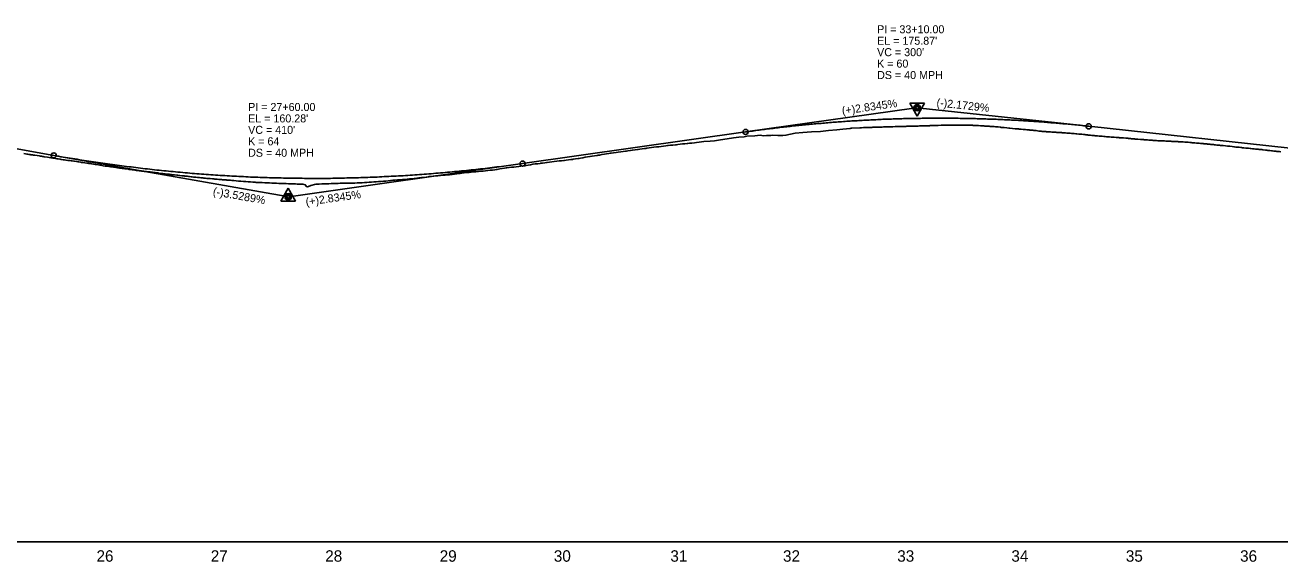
# Model space of a CAD drawing. Extents: x 1778432 to 1784301, y 601022 to 621789.
# Drawn here: x 1782073 to 1783170, y 620022 to 620491 of the extents above; entities that cross this region are included whole.
import ezdxf

# ---------------------------------------------------------------- set-up
doc = ezdxf.new("R2010")
doc.units = 0
for name, color, linetype in [('Exist Profile Cell', 7, 'Continuous'), ('Exist Vertical Profile Ground Line', 7, 'Continuous'), ('Exist Vertical Profile Horizontal Axis Label Major', 7, 'Continuous'), ('Prop PFL VPI Symbol CELL', 7, 'Continuous'), ('Prop Vertical Profile Curve Label', 7, 'Continuous'), ('Prop Vertical Profile Grade', 7, 'Continuous'), ('Prop Vertical Profile Grade Label', 7, 'Continuous'), ('Prop VPI Label', 7, 'Continuous')]:
    doc.layers.add(name, color=color, linetype=linetype)

msp = doc.modelspace()

# ---------------------------------------------------------------- linework, layer by layer
at = {"layer": 'Exist Profile Cell'}
msp.add_line((1780143, 620039.2), (1783681.5, 620039.2), dxfattribs=at)
at = {"layer": 'Exist Vertical Profile Ground Line'}
msp.add_lwpolyline([(1782071.8, 620378.3), (1782073.3, 620378.1), (1782074.5, 620378), (1782075.2, 620377.9), (1782076.2, 620377.7), (1782077.4, 620377.5), (1782078, 620377.4), (1782078.9, 620377.3), (1782079.4, 620377.2), (1782080.4, 620377.1), (1782081.4, 620376.9), (1782083.5, 620376.6), (1782085.5, 620376.3), (1782085.8, 620376.2), (1782086.4, 620376.1), (1782087, 620376.1), (1782087.5, 620376), (1782087.9, 620375.9), (1782088.9, 620375.8), (1782089.6, 620375.6), (1782092.5, 620375.2), (1782094.1, 620374.9), (1782095.4, 620374.7), (1782096, 620374.7), (1782097.1, 620374.5), (1782098.4, 620374.3), (1782100.8, 620373.9), (1782101.7, 620373.8), (1782103.6, 620373.4), (1782104.4, 620373.3), (1782106.3, 620373), (1782106.8, 620372.9), (1782107.3, 620372.9), (1782108.7, 620372.7), (1782110.3, 620372.4), (1782110.9, 620372.3), (1782112.1, 620372.2), (1782113.3, 620372), (1782114.1, 620371.9), (1782115.5, 620371.7), (1782116.3, 620371.6), (1782117.8, 620371.4), (1782119.2, 620371.2), (1782119.5, 620371.1), (1782120, 620371.1), (1782121.6, 620370.8), (1782122.2, 620370.7), (1782123.2, 620370.6), (1782125.2, 620370.3), (1782126.8, 620370.1), (1782128.2, 620369.9), (1782128.6, 620369.8), (1782129.2, 620369.7), (1782130.2, 620369.6), (1782131.2, 620369.4), (1782134.2, 620368.9), (1782134.8, 620368.8), (1782137.2, 620368.5), (1782138.4, 620368.3), (1782139.7, 620368.1), (1782140.1, 620368), (1782141.2, 620367.8), (1782143.1, 620367.5), (1782145.1, 620367.3), (1782146.1, 620367.1), (1782147.6, 620366.9), (1782148.3, 620366.8), (1782149.1, 620366.7), (1782150.3, 620366.5), (1782152.2, 620366.2), (1782153.9, 620366), (1782155, 620365.8), (1782155.7, 620365.7), (1782156.8, 620365.6), (1782157.3, 620365.5), (1782158, 620365.4), (1782160.3, 620365.1), (1782161.3, 620365), (1782163.4, 620364.7), (1782164, 620364.6), (1782166, 620364.4), (1782167, 620364.2), (1782168.8, 620364), (1782169.9, 620363.8), (1782170.5, 620363.7), (1782172.1, 620363.6), (1782172.5, 620363.5), (1782172.9, 620363.4), (1782174.5, 620363.2), (1782175.1, 620363.1), (1782175.9, 620363), (1782176.6, 620362.9), (1782177.4, 620362.8), (1782178.9, 620362.6), (1782179.6, 620362.5), (1782180.9, 620362.4), (1782181.9, 620362.3), (1782182.8, 620362.1), (1782184.1, 620362), (1782184.9, 620361.9), (1782186.4, 620361.7), (1782187, 620361.6), (1782188.2, 620361.5), (1782188.5, 620361.4), (1782189.1, 620361.4), (1782189.7, 620361.3), (1782191.1, 620361.1), (1782192.9, 620360.9), (1782193.2, 620360.9), (1782193.8, 620360.8), (1782194.1, 620360.8), (1782195.3, 620360.6), (1782197.4, 620360.4), (1782198.9, 620360.3), (1782199.5, 620360.2), (1782200.2, 620360.1), (1782200.8, 620360), (1782201.5, 620359.9), (1782202.1, 620359.9), (1782203, 620359.8), (1782203.6, 620359.7), (1782205.7, 620359.5), (1782206.1, 620359.4), (1782206.6, 620359.4), (1782207.8, 620359.3), (1782208.4, 620359.2), (1782209.9, 620359), (1782212, 620358.8), (1782212.7, 620358.7), (1782214, 620358.5), (1782215, 620358.5), (1782216.1, 620358.3), (1782216.8, 620358.3), (1782218.3, 620358), (1782219, 620358), (1782220.2, 620357.9), (1782220.9, 620357.8), (1782222.3, 620357.7), (1782223.8, 620357.5), (1782224.4, 620357.5), (1782225.4, 620357.4), (1782226.7, 620357.3), (1782227.5, 620357.2), (1782228.5, 620357.1), (1782229.2, 620357), (1782229.9, 620356.9), (1782230.6, 620356.9), (1782232, 620356.7), (1782232.7, 620356.7), (1782233.5, 620356.6), (1782234.8, 620356.5), (1782236.8, 620356.3), (1782237.3, 620356.3), (1782237.9, 620356.2), (1782238.9, 620356.1), (1782239.4, 620356.1), (1782239.9, 620356), (1782240.9, 620355.9), (1782242.4, 620355.8), (1782243.2, 620355.7), (1782244.1, 620355.7), (1782245.1, 620355.6), (1782245.4, 620355.5), (1782247.2, 620355.4), (1782247.9, 620355.3), (1782248.7, 620355.3), (1782249.3, 620355.2), (1782251.3, 620355.1), (1782252.6, 620355), (1782253.7, 620354.9), (1782254.5, 620354.8), (1782255.5, 620354.8), (1782257.4, 620354.6), (1782259.6, 620354.4), (1782261.7, 620354.2), (1782263.8, 620354.1), (1782265.9, 620353.9), (1782268.1, 620353.7), (1782270, 620353.6), (1782272.1, 620353.4), (1782274.2, 620353.3), (1782275, 620353.2), (1782276.2, 620353.2), (1782278.3, 620353.1), (1782279.6, 620353), (1782280.4, 620353), (1782282.5, 620352.9), (1782284.6, 620352.8), (1782286.2, 620352.7), (1782286.6, 620352.7), (1782288.7, 620352.6), (1782290.8, 620352.5), (1782291.6, 620352.4), (1782292.9, 620352.4), (1782294.9, 620352.3), (1782296.4, 620352.3), (1782297, 620352.2), (1782299.1, 620352.2), (1782300.8, 620352.1), (1782301.2, 620352.1), (1782303.2, 620352), (1782304.1, 620352), (1782305.3, 620352), (1782307.4, 620351.9), (1782308.7, 620351.9), (1782309.5, 620351.8), (1782310.8, 620351.6), (1782311.5, 620351.7), (1782312.5, 620351.7), (1782313.6, 620351.7), (1782315.7, 620351.6), (1782318, 620351.2), (1782318.9, 620349.7), (1782320, 620349.2), (1782322.2, 620350.2), (1782322.8, 620350.5), (1782324, 620350.7), (1782326.1, 620351.3), (1782327.1, 620351.6), (1782328.1, 620351.6), (1782329.2, 620351.7), (1782330.2, 620351.7), (1782332.3, 620351.8), (1782334.4, 620351.9), (1782334.7, 620351.9), (1782336.4, 620352), (1782338.5, 620352), (1782340.6, 620352.1), (1782342.9, 620352.2), (1782344.7, 620352.3), (1782346.8, 620352.3), (1782348.4, 620352.4), (1782348.9, 620352.4), (1782351, 620352.5), (1782353, 620352.6), (1782354.1, 620352.6), (1782355.1, 620352.6), (1782357.2, 620352.6), (1782359.3, 620352.6), (1782361.4, 620352.6), (1782363.4, 620352.7), (1782365.5, 620352.8), (1782367.6, 620352.9), (1782369.7, 620353.1), (1782371.7, 620353.2), (1782373.8, 620353.4), (1782375.2, 620353.5), (1782375.9, 620353.5), (1782378, 620353.7), (1782380, 620353.8), (1782382.1, 620353.9), (1782382.9, 620353.9), (1782384.2, 620354.1), (1782386.3, 620354.2), (1782388.3, 620354.4), (1782390.4, 620354.6), (1782392.5, 620354.8), (1782393.1, 620354.9), (1782394.6, 620355), (1782396.6, 620355.2), (1782398.7, 620355.4), (1782399.1, 620355.5), (1782400.8, 620355.5), (1782402.9, 620355.6), (1782403.6, 620355.7), (1782404.9, 620355.8), (1782407, 620356), (1782409.1, 620356.2), (1782409.6, 620356.3), (1782411.2, 620356.4), (1782413.2, 620356.7), (1782415.6, 620356.9), (1782417.4, 620357.1), (1782419.5, 620357.4), (1782420.5, 620357.5), (1782421.5, 620357.6), (1782423.6, 620357.9), (1782425.7, 620358.1), (1782426.4, 620358.2), (1782427.8, 620358.3), (1782429.8, 620358.5), (1782431.9, 620358.8), (1782432.2, 620358.8), (1782434, 620359), (1782436.1, 620359.2), (1782437.8, 620359.4), (1782438.1, 620359.5), (1782440.2, 620359.6), (1782442.3, 620359.8), (1782443.9, 620359.9), (1782444.4, 620360), (1782446.5, 620360.2), (1782448.5, 620360.5), (1782450.6, 620360.7), (1782452.7, 620360.9), (1782453.5, 620361), (1782454.8, 620361.2), (1782456.8, 620361.4), (1782458.9, 620361.7), (1782461.2, 620361.9), (1782463.1, 620362.1), (1782465.1, 620362.3), (1782467.2, 620362.5), (1782469.5, 620362.7), (1782471.4, 620362.9), (1782473.4, 620363.1), (1782475.5, 620363.3), (1782477.6, 620363.5), (1782479.7, 620363.8), (1782480.1, 620363.8), (1782481.7, 620364), (1782483.8, 620364.2), (1782485, 620364.4), (1782485.9, 620364.5), (1782488, 620364.9), (1782490, 620365.3), (1782492.1, 620365.6), (1782493.6, 620365.9), (1782494.2, 620365.9), (1782496.3, 620366.2), (1782498.3, 620366.4), (1782499.2, 620366.5), (1782500.4, 620366.6), (1782502.5, 620366.9), (1782504.8, 620367.2), (1782506.6, 620367.4), (1782508.7, 620367.7), (1782510, 620367.8), (1782510.8, 620368), (1782512.9, 620368.3), (1782514.9, 620368.6), (1782517, 620369), (1782519.1, 620369.3), (1782521.2, 620369.5), (1782523.3, 620369.8), (1782523.6, 620369.9), (1782525.3, 620370.1), (1782527.4, 620370.4), (1782528.8, 620370.6), (1782529.5, 620370.7), (1782531.6, 620371), (1782533.6, 620371.2), (1782535.7, 620371.5), (1782537.8, 620371.7), (1782539.9, 620371.9), (1782541.9, 620372.1), (1782544, 620372.3), (1782544.7, 620372.4), (1782546.1, 620372.5), (1782548.2, 620372.8), (1782550.2, 620373.1), (1782551.7, 620373.3), (1782552.3, 620373.4), (1782554.4, 620373.7), (1782556.5, 620374), (1782557.4, 620374.1), (1782558.5, 620374.3), (1782560.6, 620374.7), (1782562.7, 620375.1), (1782564.8, 620375.5), (1782566.8, 620375.8), (1782568.4, 620376.1), (1782568.9, 620376.2), (1782571, 620376.5), (1782573.1, 620376.8), (1782574.2, 620377), (1782575.1, 620377.1), (1782577.2, 620377.5), (1782579.5, 620377.8), (1782581.4, 620378.1), (1782583.4, 620378.4), (1782584.5, 620378.6), (1782585.5, 620378.8), (1782587.6, 620379.1), (1782589.7, 620379.4), (1782591.7, 620379.7), (1782593.8, 620380), (1782595.9, 620380.2), (1782598, 620380.5), (1782598.8, 620380.6), (1782600.1, 620380.8), (1782602.1, 620381), (1782603.8, 620381.3), (1782604.2, 620381.3), (1782606.3, 620381.6), (1782608.4, 620381.9), (1782609.1, 620382), (1782610.4, 620382.1), (1782612.5, 620382.4), (1782614.6, 620382.7), (1782615.7, 620382.8), (1782616.7, 620383), (1782618.7, 620383.3), (1782620.8, 620383.6), (1782622.9, 620383.9), (1782625, 620384.2), (1782626.6, 620384.4), (1782627, 620384.4), (1782629.1, 620384.7), (1782631.2, 620384.9), (1782633.3, 620385.1), (1782634.6, 620385.3), (1782635.3, 620385.4), (1782637.4, 620385.6), (1782639.5, 620385.8), (1782641.6, 620386), (1782642.6, 620386.1), (1782643.6, 620386.3), (1782645.8, 620386.6), (1782647.8, 620386.8), (1782649.9, 620386.9), (1782651.9, 620387.1), (1782652.5, 620387.2), (1782654, 620387.4), (1782656.1, 620387.6), (1782658.2, 620387.9), (1782660.2, 620388.1), (1782662.3, 620388.4), (1782664.4, 620388.6), (1782666.5, 620388.9), (1782671.9, 620389.3), (1782675.7, 620389.6), (1782679.4, 620390), (1782692.5, 620392), (1782697.2, 620392.6), (1782701.7, 620393.1), (1782704, 620393.5), (1782711.1, 620394), (1782715.8, 620394.4), (1782718.7, 620394), (1782721.4, 620394.2), (1782725.2, 620394.2), (1782726.5, 620394.4), (1782731.3, 620394.2), (1782735.7, 620394.2), (1782738.2, 620394.4), (1782746.3, 620396.1), (1782753, 620396.8), (1782760.7, 620397.5), (1782768.4, 620397.7), (1782775.5, 620398.5), (1782782.7, 620399.2), (1782788, 620399.8), (1782794.5, 620400.4), (1782795.4, 620400.5), (1782795.8, 620400.5), (1782802.8, 620400.9), (1782804.3, 620401), (1782806.2, 620401.1), (1782808, 620401.2), (1782808.7, 620401.2), (1782811.4, 620401.3), (1782813.6, 620401.3), (1782814.1, 620401.4), (1782816.1, 620401.4), (1782816.8, 620401.4), (1782818.6, 620401.5), (1782819.6, 620401.5), (1782821.2, 620401.5), (1782822.3, 620401.5), (1782823.7, 620401.6), (1782825, 620401.6), (1782826.2, 620401.6), (1782827.1, 620401.7), (1782828.7, 620401.7), (1782830.5, 620401.7), (1782831.2, 620401.7), (1782831.8, 620401.8), (1782833.7, 620401.9), (1782834.1, 620401.9), (1782836.2, 620401.9), (1782838.7, 620402), (1782839.4, 620402), (1782841.2, 620402.1), (1782843.4, 620402.1), (1782843.7, 620402.2), (1782845.7, 620402.2), (1782846.2, 620402.2), (1782846.8, 620402.2), (1782848.7, 620402.3), (1782849.6, 620402.3), (1782851.2, 620402.3), (1782852.7, 620402.4), (1782853.8, 620402.4), (1782855, 620402.5), (1782856.3, 620402.5), (1782857.7, 620402.6), (1782858.8, 620402.6), (1782859.7, 620402.7), (1782861.3, 620402.7), (1782863.2, 620402.7), (1782863.8, 620402.7), (1782864.3, 620402.8), (1782866.3, 620402.8), (1782868.8, 620402.9), (1782870.7, 620403), (1782871.3, 620403), (1782873.9, 620403.1), (1782876.5, 620403.1), (1782878.5, 620403.1), (1782878.8, 620403.1), (1782880.6, 620403.1), (1782881.3, 620403.1), (1782882.3, 620403.1), (1782883.9, 620403.1), (1782885, 620403.1), (1782886.4, 620403.2), (1782887.5, 620403.2), (1782888.9, 620403.2), (1782889.9, 620403.2), (1782891.4, 620403.2), (1782893.2, 620403.1), (1782893.9, 620403.1), (1782894.5, 620403.1), (1782896.4, 620403.1), (1782896.8, 620403.1), (1782898.9, 620403.1), (1782901.4, 620403.1), (1782902, 620403), (1782904, 620403), (1782906, 620402.8), (1782906.6, 620402.8), (1782908.3, 620402.7), (1782908.8, 620402.6), (1782910.4, 620402.5), (1782911.2, 620402.5), (1782912.3, 620402.4), (1782913.2, 620402.4), (1782915, 620402.2), (1782915.9, 620402.2), (1782916.9, 620402.1), (1782918.3, 620402), (1782919, 620402), (1782920.4, 620401.9), (1782921.5, 620401.8), (1782922.3, 620401.7), (1782924, 620401.6), (1782925.9, 620401.4), (1782926.5, 620401.3), (1782927, 620401.3), (1782929, 620401.1), (1782931.5, 620400.8), (1782933.2, 620400.7), (1782934.1, 620400.6), (1782936.5, 620400.4), (1782938.6, 620400.1), (1782939, 620400.1), (1782940.9, 620399.9), (1782941.5, 620399.9), (1782942.3, 620399.8), (1782944, 620399.6), (1782945.6, 620399.5), (1782946.6, 620399.4), (1782947.9, 620399.3), (1782949.1, 620399.1), (1782950.4, 620399), (1782950.9, 620399), (1782951.6, 620398.9), (1782953.2, 620398.8), (1782954.1, 620398.7), (1782955, 620398.6), (1782956.6, 620398.4), (1782957.1, 620398.4), (1782959.4, 620398.1), (1782961.2, 620397.9), (1782961.6, 620397.9), (1782962.4, 620397.8), (1782963.3, 620397.8), (1782964.1, 620397.7), (1782965.4, 620397.6), (1782966.2, 620397.5), (1782966.6, 620397.5), (1782967.4, 620397.5), (1782968.5, 620397.4), (1782969.2, 620397.3), (1782969.5, 620397.3), (1782970.7, 620397.2), (1782971.7, 620397.2), (1782973, 620397.1), (1782973.6, 620397), (1782974.2, 620397), (1782975.2, 620396.9), (1782975.7, 620396.9), (1782976.7, 620396.8), (1782977.4, 620396.8), (1782977.7, 620396.8), (1782979.3, 620396.7), (1782979.8, 620396.6), (1782981.9, 620396.5), (1782982.6, 620396.4), (1782983.9, 620396.3), (1782984.3, 620396.3), (1782986.3, 620396.1), (1782986.8, 620396.1), (1782988.1, 620396), (1782988.5, 620395.9), (1782989.4, 620395.9), (1782990.4, 620395.8), (1782991.9, 620395.7), (1782992.2, 620395.6), (1782992.7, 620395.6), (1782994.3, 620395.4), (1782994.9, 620395.4), (1782996.3, 620395.2), (1782997, 620395.2), (1782998.4, 620395), (1782999.5, 620394.9), (1783000.5, 620394.8), (1783001.5, 620394.7), (1783002, 620394.7), (1783002.5, 620394.6), (1783003.6, 620394.5), (1783004.6, 620394.4), (1783005.9, 620394.3), (1783006.6, 620394.2), (1783007.1, 620394.2), (1783007.9, 620394.1), (1783008.7, 620394), (1783009.7, 620393.9), (1783010.1, 620393.9), (1783010.8, 620393.8), (1783012.2, 620393.7), (1783012.8, 620393.6), (1783014.3, 620393.5), (1783014.9, 620393.5), (1783016.4, 620393.3), (1783017, 620393.3), (1783017.3, 620393.3), (1783018.5, 620393.1), (1783019, 620393.1), (1783019.9, 620393), (1783020.6, 620393), (1783021.1, 620392.9), (1783022.7, 620392.8), (1783023.2, 620392.8), (1783024, 620392.7), (1783025.2, 620392.6), (1783026.9, 620392.5), (1783027.6, 620392.4), (1783029, 620392.3), (1783029.3, 620392.3), (1783030.1, 620392.2), (1783031.4, 620392.1), (1783032, 620392.1), (1783032.7, 620392), (1783033.5, 620392), (1783035.5, 620391.8), (1783037.3, 620391.7), (1783037.9, 620391.6), (1783038.8, 620391.5), (1783039.7, 620391.5), (1783040.4, 620391.4), (1783041.7, 620391.3), (1783042.3, 620391.2), (1783043, 620391.2), (1783043.8, 620391.1), (1783045.1, 620391), (1783045.9, 620391), (1783048.2, 620390.8), (1783049.6, 620390.7), (1783050, 620390.7), (1783050.8, 620390.6), (1783051.6, 620390.5), (1783052, 620390.5), (1783053.4, 620390.4), (1783054.1, 620390.3), (1783054.5, 620390.3), (1783055.5, 620390.2), (1783056.2, 620390.2), (1783057.3, 620390.1), (1783058.2, 620390), (1783058.6, 620390), (1783059.4, 620389.9), (1783060.3, 620389.9), (1783061.1, 620389.8), (1783061.5, 620389.8), (1783062.4, 620389.7), (1783063.6, 620389.6), (1783064.5, 620389.6), (1783066.1, 620389.5), (1783066.5, 620389.5), (1783068, 620389.4), (1783068.8, 620389.4), (1783069.2, 620389.4), (1783070.6, 620389.3), (1783071.8, 620389.2), (1783072.7, 620389.2), (1783073.7, 620389.1), (1783074.3, 620389.1), (1783074.7, 620389.1), (1783075.7, 620389), (1783077, 620389), (1783077.7, 620389), (1783078.9, 620388.9), (1783079.8, 620388.8), (1783080.9, 620388.8), (1783081.6, 620388.7), (1783082.2, 620388.7), (1783083, 620388.6), (1783083.6, 620388.6), (1783085.1, 620388.5), (1783085.5, 620388.5), (1783087.1, 620388.4), (1783087.5, 620388.4), (1783089.4, 620388.2), (1783090.1, 620388.2), (1783091.4, 620388.1), (1783092.8, 620388), (1783093.3, 620387.9), (1783094.9, 620387.8), (1783095.4, 620387.8), (1783095.8, 620387.8), (1783097.4, 620387.6), (1783098.1, 620387.5), (1783099.2, 620387.4), (1783099.5, 620387.4), (1783100.8, 620387.3), (1783101.6, 620387.2), (1783102, 620387.2), (1783103.1, 620387.1), (1783103.6, 620387), (1783104.4, 620387), (1783105.7, 620386.8), (1783106.2, 620386.8), (1783106.9, 620386.7), (1783107.8, 620386.6), (1783108.9, 620386.5), (1783109.8, 620386.4), (1783110.7, 620386.4), (1783112.1, 620386.2), (1783112.9, 620386.1), (1783114, 620386), (1783115.2, 620385.8), (1783115.6, 620385.8), (1783116.1, 620385.7), (1783117.6, 620385.6), (1783118.1, 620385.5), (1783118.7, 620385.5), (1783119.4, 620385.4), (1783120.1, 620385.3), (1783120.7, 620385.3), (1783122.7, 620385.1), (1783124.3, 620384.9), (1783125.1, 620384.9), (1783125.9, 620384.8), (1783126.3, 620384.8), (1783128.4, 620384.6), (1783129.8, 620384.4), (1783130.5, 620384.3), (1783131.8, 620384.1), (1783132.5, 620384.1), (1783133.3, 620384), (1783134.6, 620383.9), (1783136, 620383.7), (1783136.7, 620383.6), (1783137.4, 620383.5), (1783138.8, 620383.4), (1783140.4, 620383.2), (1783140.8, 620383.2), (1783141.6, 620383.1), (1783142.8, 620383), (1783144.3, 620382.8), (1783144.9, 620382.7), (1783146.3, 620382.6), (1783147.1, 620382.5), (1783147.8, 620382.4), (1783149, 620382.3), (1783149.9, 620382.2), (1783151.1, 620382.1), (1783152, 620382), (1783152.6, 620381.9), (1783153.2, 620381.9), (1783154.3, 620381.8), (1783155.4, 620381.6), (1783157.5, 620381.4), (1783158.2, 620381.4), (1783159, 620381.3), (1783159.4, 620381.2), (1783161.1, 620381), (1783161.4, 620381), (1783163, 620380.8), (1783163.8, 620380.7), (1783164.8, 620380.6), (1783165.5, 620380.5), (1783166.7, 620380.4), (1783167.6, 620380.3), (1783168.3, 620380.3), (1783169.7, 620380.2), (1783170.9, 620380)], dxfattribs=at)
at = {"layer": 'Prop PFL VPI Symbol CELL'}
for p, q in [((1782853, 620411.1), (1782846.5, 620422.3)), ((1782859.4, 620422.3), (1782846.5, 620422.3)), ((1782853, 620411.1), (1782859.4, 620422.3)), ((1782303, 620348.1), (1782296.5, 620336.9)), ((1782303, 620348.1), (1782309.5, 620336.9)), ((1782296.5, 620336.9), (1782309.5, 620336.9))]:
    msp.add_line(p, q, dxfattribs=at)
for centre, radius in [((1782853, 620418.5), 1.75), ((1782853, 620418.5), 1.2), ((1782303, 620340.6), 1.75), ((1782303, 620340.6), 1.2)]:
    msp.add_circle(centre, radius, dxfattribs=at)
at = {"layer": 'Prop Vertical Profile Curve Label'}
for centre in [(1783003, 620402.2), (1782703, 620397.3), (1782098, 620376.8), (1782508, 620369.6)]:
    msp.add_circle(centre, 2.25, dxfattribs=at)
at = {"layer": 'Prop Vertical Profile Grade'}
for p, q in [((1783003, 620402.2), (1783430.5, 620355.8)), ((1782508, 620369.6), (1782703, 620397.3)), ((1782048, 620385.6), (1782098, 620376.8))]:
    msp.add_line(p, q, dxfattribs=at)
for points in [[(1782703, 620397.3), (1782709, 620398.1), (1782715, 620398.9), (1782721, 620399.7), (1782727, 620400.4), (1782733, 620401.2), (1782739, 620401.8), (1782745, 620402.5), (1782751, 620403.1), (1782757, 620403.7), (1782763, 620404.3), (1782769, 620404.8), (1782775, 620405.3), (1782781, 620405.8), (1782787, 620406.2), (1782793, 620406.7), (1782799, 620407), (1782805, 620407.4), (1782811, 620407.7), (1782817, 620408), (1782823, 620408.3), (1782829, 620408.5), (1782835, 620408.7), (1782841, 620408.9), (1782847, 620409), (1782853, 620409.1), (1782859, 620409.2), (1782865, 620409.3), (1782871, 620409.3), (1782877, 620409.3), (1782883, 620409.3), (1782889, 620409.2), (1782895, 620409.1), (1782901, 620409), (1782907, 620408.8), (1782913, 620408.6), (1782919, 620408.4), (1782925, 620408.2), (1782931, 620407.9), (1782937, 620407.6), (1782943, 620407.3), (1782949, 620406.9), (1782955, 620406.5), (1782961, 620406.1), (1782967, 620405.6), (1782973, 620405.1), (1782979, 620404.6), (1782985, 620404.1), (1782991, 620403.5), (1782997, 620402.9), (1783003, 620402.2)], [(1782098, 620376.8), (1782106.2, 620375.3), (1782114.4, 620374), (1782122.6, 620372.7), (1782130.8, 620371.4), (1782139, 620370.2), (1782147.2, 620369), (1782155.4, 620367.9), (1782163.6, 620366.9), (1782171.8, 620365.9), (1782180, 620364.9), (1782188.2, 620364), (1782196.4, 620363.2), (1782204.6, 620362.4), (1782212.8, 620361.6), (1782221, 620360.9), (1782229.2, 620360.3), (1782237.4, 620359.7), (1782245.6, 620359.2), (1782253.8, 620358.7), (1782262, 620358.3), (1782270.2, 620357.9), (1782278.4, 620357.6), (1782286.6, 620357.3), (1782294.8, 620357.1), (1782303, 620356.9), (1782311.2, 620356.8), (1782319.4, 620356.7), (1782327.6, 620356.7), (1782335.8, 620356.7), (1782344, 620356.8), (1782352.2, 620357), (1782360.4, 620357.2), (1782368.6, 620357.4), (1782376.8, 620357.7), (1782385, 620358.1), (1782393.2, 620358.5), (1782401.4, 620358.9), (1782409.6, 620359.5), (1782417.8, 620360), (1782426, 620360.6), (1782434.2, 620361.3), (1782442.4, 620362), (1782450.6, 620362.8), (1782458.8, 620363.6), (1782467, 620364.5), (1782475.2, 620365.4), (1782483.4, 620366.4), (1782491.6, 620367.4), (1782499.8, 620368.5), (1782508, 620369.6)]]:
    msp.add_spline(points, degree=3, dxfattribs=at)
at = {"layer": 'Prop VPI Label'}
for p, q in [((1782703, 620397.3), (1782850.2, 620418.1)), ((1783003, 620402.2), (1782855.7, 620418.2)), ((1782098, 620376.8), (1782300.3, 620341.1)), ((1782508, 620369.6), (1782305.7, 620341))]:
    msp.add_line(p, q, dxfattribs=at)
for centre in [(1782853, 620418.5), (1782303, 620340.6), (1782303, 620340.6)]:
    msp.add_circle(centre, 2.75, dxfattribs=at)

# ---------------------------------------------------------------- texts
at = {"layer": 'Exist Vertical Profile Horizontal Axis Label Major'}
for s, p in [('26', (1782135.4, 620021.7)), ('27', (1782235.3, 620021.7)), ('28', (1782335.4, 620021.7)), ('29', (1782435.5, 620021.7)), ('30', (1782535.3, 620021.7)), ('31', (1782637.2, 620021.7)), ('32', (1782735.7, 620021.7)), ('33', (1782835.6, 620021.7)), ('34', (1782935.4, 620021.7)), ('35', (1783035.5, 620021.7)), ('36', (1783135.4, 620021.7))]:
    msp.add_text(s, height=10, dxfattribs=at).set_placement(p)
at = {"layer": 'Prop Vertical Profile Curve Label'}
for s, p in [("VC = 300'", (1782818, 620463.5)), ('K = 60', (1782818, 620453.5)), ('DS = 40 MPH', (1782818, 620443.5)), ("VC = 410'", (1782268, 620395.6)), ('K = 64', (1782268, 620385.6)), ('DS = 40 MPH', (1782268, 620375.6))]:
    msp.add_text(s, height=7, dxfattribs=at).set_placement(p)
at = {"layer": 'Prop Vertical Profile Grade Label'}
for s, rotation, p in [('(+)2.8345%', 8.066, (1782787.7, 620412.3)), ('(-)2.1729%', 353.7998, (1782869.7, 620419.7)), ('(-)3.5289%', 349.9933, (1782236.8, 620342.1)), ('(+)2.8345%', 8.066, (1782318.8, 620332.7))]:
    msp.add_text(s, height=7, rotation=rotation, dxfattribs=at).set_placement(p)
at = {"layer": 'Prop VPI Label'}
for s, p in [('PI = 33+10.00', (1782818, 620483.5)), ("EL = 175.87'", (1782818, 620473.5)), ('PI = 27+60.00', (1782268, 620415.6)), ("EL = 160.28'", (1782268, 620405.6))]:
    msp.add_text(s, height=7, dxfattribs=at).set_placement(p)

doc.saveas('drawing.dxf')
